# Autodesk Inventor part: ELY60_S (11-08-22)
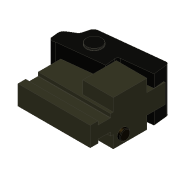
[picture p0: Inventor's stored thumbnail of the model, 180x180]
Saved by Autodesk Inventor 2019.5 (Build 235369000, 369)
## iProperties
Created: 2022-08
Part Number: ELY60_S (11-08-22)
Material: St37-2 / S235
Document SubType Name: Modeling
Designer: schoth
Density: 7.86 g/cm^3
Appearance: Steel
RuleStatus: InUse
Author: schoth
Mass(KG): 0.0
Area(mm): 0.0
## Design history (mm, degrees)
derived "ELY60.iam"
body "Solid1"
node "FB195-005.ipt:1"
node "ELY60-88.iam:1::FB199-030.ipt:1"
node "ELY60-88.iam:1::CS235-006.ipt:1"
node "ELY60-99.iam:1::FB196-011.ipt:1"
node "ELY60-99.iam:1::FB197-104.ipt:1"
node "ELY60.iam_Bodies"
